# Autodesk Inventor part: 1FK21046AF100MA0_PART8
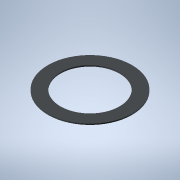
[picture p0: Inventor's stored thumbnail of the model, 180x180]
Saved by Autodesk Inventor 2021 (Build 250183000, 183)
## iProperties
Created: 2025-04
Part Number: 1FK21046AF100MA0_PART8
Material: Generic
Catalog Web Link: www.3dfindit.com
Description: -Servo synchronous motor
Document SubType Name: Modeling
Designer: psAdmin
Mass: 0.27214 g
Surface Area: 11.8752 cm^2
Volume: 0.27214 cm^3
Density: 1 g/cm^3
Appearance: PSOLRGB-212-217-219
Category: PARTsolutions
Title: 1FK21046AF100MA0_PART8
Author: Cadenas PARTsolutions
Comments: Servo synchronous motor
Sending System: PARTsolutions
Preprocessor: ST-DEVELOPER v19.3
PSOL_IDENT_0: {$CADENAS_DATA/23d-libs/siemens_ag/_cat_/4f/2b/1fk21046af100ma0.prj},213 {VTYP=3D},{NB=1FK21046AF100
PSOL_IDENT_1: MA0_PART8},{LINA=1FK21046AF100MA0_PART8},{NN=1FK21046AF100MA0_PART8},{NOPRJ=TRUE},{DATE=19.08.2025 1
PSOL_IDENT_2: 4:00:37},{GEOMDATE=30.07.2025 02:01:06},{VERSION=},{LINEID=10},{WBVAR=},{WBNUMERIC=}  {NB=1FK21046AF
PSOL_IDENT_3: 100MA0_PART8},{LINA=1FK21046AF100MA0_PART8},{KT=DUMMY},{PREVIEW=../../../_pool_/cb/72/p_d211_xx_0043
PSOL_IDENT_4: 4j.png},{DESCSHORT=SIMOTICS S-1FK2 HD, SINAMICS S210 3AC 400V-480V, 3.2 Nm, 3000 rpm},{DESCLONG=SIMO
PSOL_IDENT_5: TICS S-1FK2 HD servo motor M0=3.2 Nm; PN = 1 kW at nN=3000 rpm (380-480 V); PN = 0.5 kW at nN=1500 r
PSOL_IDENT_6: pm (200-240 V); with holding brake; degree of protection IP64; cylindrical shaft D19x40mm; absolute
PSOL_IDENT_7: encoder 22-bit + 12-bit multiturn (encoder AM22DQC); with OCC interface; plug size M17, rotatable; S
PSOL_IDENT_8: IMOTICS S-1FK2 servomotorfor a wide range of uses in industrial environments. SIMOTICS S‑1FK2 servom
PSOL_IDENT_9: otors are compact synchronous motors with a high dynamic performance that set themselves apart as a
PSOL_IDENT_10: result of their high power density, degree of protection and overload capability. The motors are ava
PSOL_IDENT_11: ilable in two variants: as High Dynamic variant (highest dynamic performance as a result of the low
PSOL_IDENT_12: intrinsic moment of inertia for applications demanding a high dynamic performance with low moved mas
PSOL_IDENT_13: ses) - and as Compact variant (precise and stable closed-loop control for medium up to large moved m
PSOL_IDENT_14: asses as a result of a medium intrinsic moment of inertia). SIMOTICSS‑1FK2 servomotors fully exploit
PSOL_IDENT_15: their strengths in a system with the SINAMICSS210 frequency converter and simple connection using t
PSOL_IDENT_16: he one cable connection (OCC). Advantages include the short control and positioning times, fast and
PSOL_IDENT_17: precise correction of disturbing quantities as well as stable control with a high dynamic performanc
PSOL_IDENT_18: e. The servo motors can be configured to address a wide range of requirements. For example with and
PSOL_IDENT_19: without holding brake, IP64 or IP65 degree of protection, singleturn or multiturn absolute encoders
PSOL_IDENT_20: - to name just a few. Further, the servomotors are available in different shaft heights extending fr
PSOL_IDENT_21: om 20 to 100. A shaft sealing ring is available to achieve an IP65 degree of protection and for subs
PSOL_IDENT_22: equent mounting at the motor or as spare part. SIMOTICS - the optimum motor for each and every motio
PSOL_IDENT_23: n control application.},{INTNO=195125049673},{SUPPLIERALTNO=1FK2104-6AF10-0MA0},{MANUID=1FK21046AF10
PSOL_IDENT_24: 0MA0},{MANUNAME=Siemens},{MANUTYPEDESC=Synchronous motor 1FK2-HD 3.2 NM},{AAU732=SIMOTICS},{AAO057=S
PSOL_IDENT_25: -1FK2},{AAU734=SIMOTICS S-1FK2 HD servo motor M0=3.2 Nm; PN = 1 kW at nN=3000 rpm (380-480 V); PN =
PSOL_IDENT_26: 0.5 kW at nN=1500 rpm (200-240 V); with holding brake; degree of protection IP64; cylindrical shaft
PSOL_IDENT_27: D19x40mm; absolute encoder 22-bit + 12-bit multiturn (encoder AM22DQC); with OCC interface; plug siz
PSOL_IDENT_28: e M17, rotatable;},{AAW338=Synchronous motor 1FK2-HD 3.2 NM},{AAO742=SIMOTICS},{AAO663=4042948694534
PSOL_IDENT_29: },{NOCUPEROU=1},{PRICEQUANTITY=1},{QUANTITYMIN=1},{QUANTITYINT=1},{CTN=85015220},{COO=DE},{AAO676=1F
PSOL_IDENT_30: K2104-6AF10-0MA0},{AAO677=Siemens AG},{ORDERUNIT=C62},{CONTENTUNIT=C62}
NB: 1FK21046AF100MA0_PART8
NT: Servo synchronous motor
NBSYN: $MANUID._PART8
LINA: 1FK21046AF100MA0_PART8
CATALOG: SIEMENS
PREVIEW: ../../../_pool_/cb/72/p_d211_xx_00434j.png
DESCSHORT: SIMOTICS S-1FK2 HD, SINAMICS S210 3AC 400V-480V, 3.2 Nm, 3000 rpm
DESCLONG: SIMOTICS S-1FK2 HD servo motor M0=3.2 Nm; PN = 1 kW at nN=3000 rpm (380-480 V); PN = 0.5 kW at nN=1500 rpm (200-240 V); with holding brake; degree of protection
INTNO: 195125049673
SUPPLIERALTNO: 1FK2104-6AF10-0MA0
MANUID: 1FK21046AF100MA0
MANUNAME: Siemens
MANUTYPEDESC: Synchronous motor 1FK2-HD 3.2 NM
AAU732: SIMOTICS
AAO057: S-1FK2
AAU734: SIMOTICS S-1FK2 HD servo motor M0=3.2 Nm; PN = 1 kW at nN=3000 rpm (380-480 V); PN = 0.5 kW at nN=1500 rpm (200-240 V); with holding brake; degree of protection
AAW338: Synchronous motor 1FK2-HD 3.2 NM
AAO742: SIMOTICS
AAO663: 4042948694534.0
NOCUPEROU: 1
PRICEQUANTITY: 1
QUANTITYMIN: 1
QUANTITYINT: 1
CTN: 85015220
COO: DE
ARTICLENO: 1FK21046AF100MA0_PART8
BOMINFO: 1FK21046AF100MA0_PART8
CREATOR: CADENAS GmbH
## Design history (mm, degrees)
feature "2025_04_17_14_59_39_0177"
body "Solid1"
